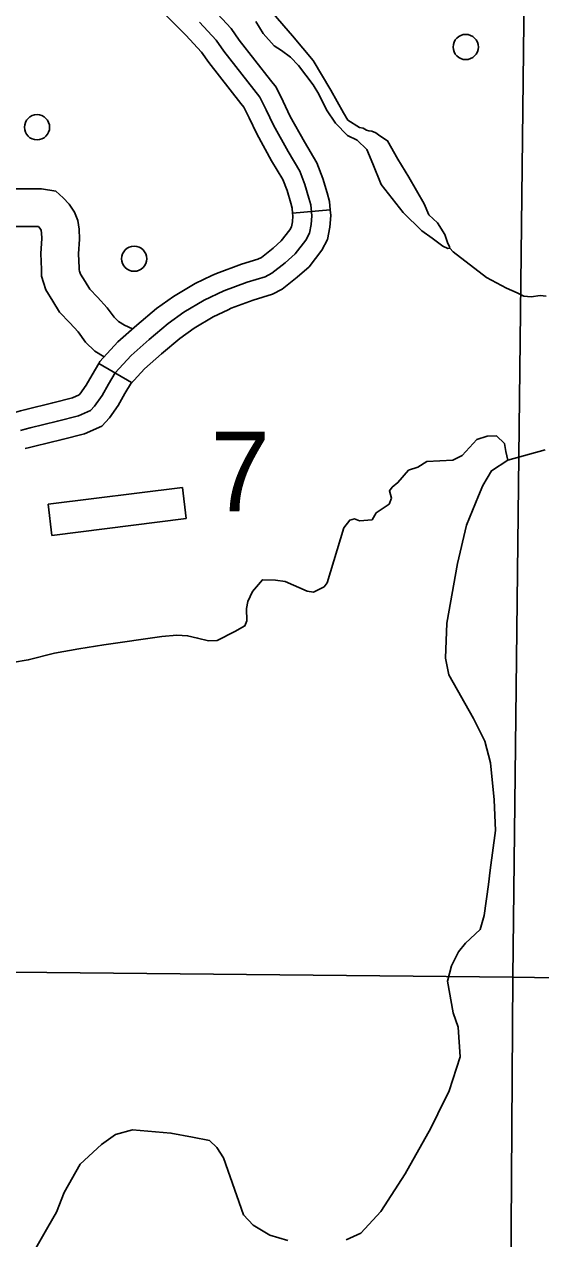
# Model space of a CAD drawing. Extents: x 1382482 to 1385815, y 1168351 to 1170484.
# Drawn here: x 1383576.4 to 1383658.5, y 1169243.6 to 1169436.4 of the extents above; entities that cross this region are included whole.
import ezdxf

# ---------------------------------------------------------------- set-up
doc = ezdxf.new("R2010")
doc.units = 0
for name, color, linetype in [('35', 7, 'Continuous'), ('45', 7, 'Continuous'), ('46', 7, 'Continuous'), ('5', 7, 'Continuous'), ('57', 7, 'Continuous'), ('Default', 7, 'Continuous')]:
    doc.layers.add(name, color=color, linetype=linetype)

msp = doc.modelspace()

# ---------------------------------------------------------------- linework, layer by layer
at = {"layer": '35'}
for points in [[(1383615.96, 1169438.06), (1383619.06, 1169434.54), (1383622.32, 1169430.62), (1383625.11, 1169425.89), (1383627.15, 1169422.31), (1383627.85, 1169421.16), (1383629.68, 1169420), (1383630.29, 1169419.88), (1383630.81, 1169419.57), (1383631.17, 1169419.45), (1383631.66, 1169419.39), (1383632.27, 1169419.15), (1383632.93, 1169418.66), (1383634.15, 1169417.88), (1383635.78, 1169414.96), (1383637.54, 1169412.11), (1383639.97, 1169407.86), (1383640.7, 1169406.1), (1383642.09, 1169404.86), (1383643.25, 1169402.98), (1383643.67, 1169401.7), (1383644, 1169401.06), (1383644.04, 1169400.81), (1383643.73, 1169400.79), (1383642.94, 1169401.16), (1383641.24, 1169402.43), (1383639.61, 1169403.58), (1383636.63, 1169406.5), (1383633.12, 1169410.93), (1383631.78, 1169414.2), (1383630.87, 1169416.51), (1383629.29, 1169417.97), (1383627.79, 1169418.71), (1383625.85, 1169420.65), (1383624.44, 1169422.76), (1383623.23, 1169425.27), (1383622.32, 1169426.76), (1383620.01, 1169429.82), (1383618.74, 1169431.16), (1383617.28, 1169432.19), (1383616.13, 1169432.97), (1383614.37, 1169434.92), (1383613.22, 1169436.8)], [(1383644.04, 1169400.81), (1383644.57, 1169400.24), (1383649.85, 1169396.16), (1383653.04, 1169394.48), (1383654.74, 1169393.74), (1383655.8, 1169393.2), (1383656.96, 1169393.08), (1383658.36, 1169393.29), (1383659.32, 1169393.23)], [(1383653.27, 1169367.16), (1383652.92, 1169368.57), (1383652.71, 1169369.84), (1383651.44, 1169371.03), (1383649.96, 1169370.96), (1383648.32, 1169370.45), (1383645.99, 1169367.91), (1383644.51, 1169367.18), (1383640.36, 1169366.94), (1383638.97, 1169366.05), (1383637.49, 1169365.56), (1383635.79, 1169363.62), (1383634.88, 1169362.89), (1383634.44, 1169362.29), (1383634.77, 1169361.13), (1383634.42, 1169360.21), (1383632.31, 1169358.79), (1383631.68, 1169357.7), (1383629.69, 1169357.53), (1383628.88, 1169357.88), (1383628.13, 1169357.63), (1383627.18, 1169356.42), (1383624.53, 1169347.71), (1383624.1, 1169347.07), (1383622.39, 1169346.21), (1383621.39, 1169346.4), (1383617.86, 1169347.9), (1383616.34, 1169348.13), (1383614.28, 1169348.18), (1383612.7, 1169346.32), (1383611.95, 1169344.71), (1383611.72, 1169343.61), (1383611.8, 1169341.65), (1383611.49, 1169340.85), (1383609.91, 1169339.98), (1383607.08, 1169338.54), (1383605.68, 1169338.51), (1383603.98, 1169338.92), (1383602.39, 1169339.3), (1383600.65, 1169339.41), (1383598.27, 1169339.19), (1383589.1, 1169337.84), (1383585.13, 1169337.2), (1383581.23, 1169336.52), (1383577.07, 1169335.46), (1383574.58, 1169335.04)], [(1383659.15, 1169368.82), (1383653.27, 1169367.16), (1383650.67, 1169365.48), (1383649.3, 1169363.13), (1383648.59, 1169361.5), (1383646.69, 1169356.85), (1383645.25, 1169350.76), (1383643.58, 1169341.27), (1383643.37, 1169335.73), (1383643.87, 1169333.09), (1383647.78, 1169326.14), (1383649.61, 1169322.55), (1383650.48, 1169319.11), (1383651.09, 1169313.27), (1383651.3, 1169308.4), (1383650.42, 1169302.1), (1383650.17, 1169299.82), (1383649.48, 1169294.87)], [(1383649.48, 1169294.87), (1383648.85, 1169292.69), (1383646.5, 1169290.5), (1383645.39, 1169289.13), (1383644.3, 1169286.89), (1383643.66, 1169284.46), (1383644.58, 1169279.46), (1383645.35, 1169277.18), (1383645.7, 1169272.46), (1383643.91, 1169267.07), (1383642.15, 1169263.41), (1383641.02, 1169261.14), (1383636.93, 1169253.89), (1383633.1, 1169247.9), (1383629.9, 1169244.47), (1383627.55, 1169243.42)], [(1383618.29, 1169243.27), (1383615.47, 1169244.12), (1383612.8, 1169245.74), (1383611.25, 1169247.36), (1383608.08, 1169256.44), (1383607.01, 1169258.04), (1383605.84, 1169259.15), (1383603.16, 1169259.68), (1383599.74, 1169260.35), (1383593.62, 1169260.84), (1383590.94, 1169260.14), (1383588.69, 1169258.52), (1383585.31, 1169255.43), (1383582.76, 1169250.91), (1383581.55, 1169247.81), (1383580.18, 1169245.43), (1383578.06, 1169241.69)]]:
    msp.add_lwpolyline(points, dxfattribs=at)
at = {"layer": '45'}
for p, q in [((1383619.07, 1169406.38), (1383625.05, 1169406.92)), ((1383588.28, 1169382.54), (1383593.47, 1169379.51))]:
    msp.add_line(p, q, dxfattribs=at)
for points in [[(1383601.51, 1169443.71), (1383603.14, 1169442.1), (1383606.43, 1169438.77), (1383609.29, 1169435.7), (1383610.56, 1169433.86), (1383615.57, 1169427.5)], [(1383597.3, 1169439.44), (1383598.9, 1169437.86), (1383602.1, 1169434.62), (1383604.6, 1169431.93), (1383605.74, 1169430.3), (1383610.85, 1169423.79)], [(1383604.26, 1169436.7), (1383606.94, 1169433.82), (1383608.15, 1169432.08)], [(1383608.15, 1169432.08), (1383613.88, 1169424.79), (1383614.86, 1169422.81), (1383616.03, 1169420.35), (1383618.34, 1169416.19), (1383620.19, 1169413.05), (1383621.02, 1169410.93), (1383621.66, 1169408.78), (1383621.97, 1169407.68), (1383622.12, 1169405.98), (1383622.01, 1169404.58), (1383621.74, 1169403.22), (1383621.17, 1169402.12), (1383619.47, 1169399.92), (1383617.88, 1169398.52), (1383615.77, 1169396.85), (1383614.71, 1169396.28), (1383611.87, 1169395.41), (1383608.13, 1169394.05), (1383605.03, 1169392.58), (1383601.77, 1169390.65), (1383599.32, 1169388.87), (1383596.29, 1169386.34), (1383593.42, 1169383.8), (1383590.88, 1169381.04), (1383589.82, 1169379.22), (1383588.82, 1169377.46), (1383587.61, 1169375.76), (1383586.97, 1169375.04), (1383585.04, 1169374.21), (1383581.71, 1169373.38), (1383577.4, 1169372.28), (1383576.57, 1169372.09), (1383575.85, 1169371.9)], [(1383615.57, 1169427.5), (1383616.44, 1169426.4), (1383617.56, 1169424.12), (1383618.7, 1169421.73), (1383620.94, 1169417.68), (1383622.9, 1169414.37), (1383623.86, 1169411.91), (1383624.55, 1169409.61), (1383624.93, 1169408.22), (1383625.05, 1169406.92)], [(1383610.85, 1169423.79), (1383611.33, 1169423.19), (1383612.16, 1169421.5), (1383613.36, 1169418.98), (1383615.73, 1169414.7), (1383617.49, 1169411.73), (1383618.18, 1169409.96), (1383618.78, 1169407.95), (1383619, 1169407.15), (1383619.07, 1169406.38)], [(1383625.05, 1169406.92), (1383625.13, 1169405.99), (1383624.98, 1169404.17), (1383624.6, 1169402.22), (1383623.71, 1169400.5), (1383621.67, 1169397.85), (1383619.8, 1169396.21), (1383617.41, 1169394.33), (1383615.87, 1169393.5), (1383612.82, 1169392.57), (1383609.29, 1169391.28), (1383608.81, 1169391.05)], [(1383619.07, 1169406.38), (1383619.11, 1169405.97), (1383619.03, 1169404.99), (1383618.88, 1169404.21), (1383618.63, 1169403.74), (1383617.27, 1169401.98), (1383615.96, 1169400.82), (1383614.12, 1169399.37), (1383613.55, 1169399.07), (1383610.92, 1169398.26), (1383606.97, 1169396.82), (1383606.23, 1169396.47)], [(1383606.23, 1169396.47), (1383603.61, 1169395.23), (1383600.13, 1169393.16), (1383597.47, 1169391.24), (1383594.33, 1169388.61), (1383591.31, 1169385.95), (1383588.46, 1169382.83), (1383588.28, 1169382.54)], [(1383608.81, 1169391.05), (1383606.44, 1169389.93), (1383603.42, 1169388.14), (1383601.16, 1169386.5), (1383598.25, 1169384.06), (1383595.52, 1169381.66), (1383593.31, 1169379.25), (1383593.46, 1169379.51)], [(1383588.28, 1169382.54), (1383587.22, 1169380.72), (1383586.29, 1169379.08), (1383585.26, 1169377.64), (1383585.17, 1169377.54), (1383584.08, 1169377.06), (1383580.98, 1169376.29), (1383576.7, 1169375.2), (1383575.86, 1169375.01), (1383575.09, 1169374.81)], [(1383593.47, 1169379.51), (1383592.42, 1169377.73), (1383591.35, 1169375.85), (1383589.96, 1169373.89), (1383588.76, 1169372.55), (1383586, 1169371.36), (1383582.45, 1169370.47), (1383578.1, 1169369.37), (1383577.28, 1169369.18), (1383576.61, 1169369)]]:
    msp.add_lwpolyline(points, dxfattribs=at)
at = {"layer": '46'}
for points in [[(1383593.63, 1169388.02), (1383592.34, 1169388.61), (1383591.4, 1169389.19), (1383590.73, 1169389.86), (1383589.61, 1169391.35), (1383588.09, 1169393.03), (1383586.85, 1169394.34), (1383586.1, 1169395.55), (1383585.39, 1169396.71), (1383585.24, 1169397.19), (1383585.17, 1169397.41), (1383585.15, 1169397.68), (1383585.07, 1169399.91), (1383585.22, 1169402.24), (1383585.17, 1169403.84), (1383584.93, 1169405.22), (1383584.42, 1169406.54), (1383583.59, 1169407.81), (1383582.61, 1169408.84), (1383581.45, 1169409.89), (1383579.16, 1169410.26), (1383574.61, 1169410.26)], [(1383589.11, 1169383.55), (1383587.64, 1169384.46), (1383586.19, 1169385.91), (1383584.98, 1169387.52), (1383583.69, 1169388.95), (1383582.06, 1169390.66), (1383580.99, 1169392.4), (1383579.89, 1169394.19), (1383579.51, 1169395.38), (1383579.2, 1169396.37), (1383579.16, 1169397.44), (1383579.06, 1169399.98), (1383579.21, 1169402.34), (1383579.18, 1169403.24), (1383579.12, 1169403.63), (1383579.06, 1169403.78), (1383578.87, 1169404.07), (1383578.69, 1169404.26), (1383578.68, 1169404.26), (1383573.93, 1169404.26)]]:
    msp.add_lwpolyline(points, dxfattribs=at)
at = {"layer": '5'}
for points in [[(1383655.87, 1169445.84), (1383654.02, 1169285.12)], [(1383469.02, 1169286.95), (1383654.02, 1169285.12)], [(1383654.02, 1169285.12), (1383653.46, 1169197.36)], [(1383654.02, 1169285.12), (1383859.61, 1169281.9)]]:
    msp.add_lwpolyline(points, dxfattribs=at)
at = {"layer": '57'}
for p, q in [((1383601.55, 1169362.85), (1383580.22, 1169360.19)), ((1383602.17, 1169357.89), (1383601.55, 1169362.85)), ((1383580.22, 1169360.19), (1383580.84, 1169355.23)), ((1383580.84, 1169355.23), (1383602.17, 1169357.89))]:
    msp.add_line(p, q, dxfattribs=at)
at = {"layer": 'Default'}
for centre in [(1383646.56, 1169432.76), (1383578.47, 1169420.02), (1383593.9, 1169399.15)]:
    msp.add_circle(centre, 2, dxfattribs=at)

# ---------------------------------------------------------------- texts
at = {"layer": '57'}
msp.add_text('7', height=12.67, dxfattribs=at).set_placement((1383606.05, 1169359.04))

doc.saveas('drawing.dxf')
